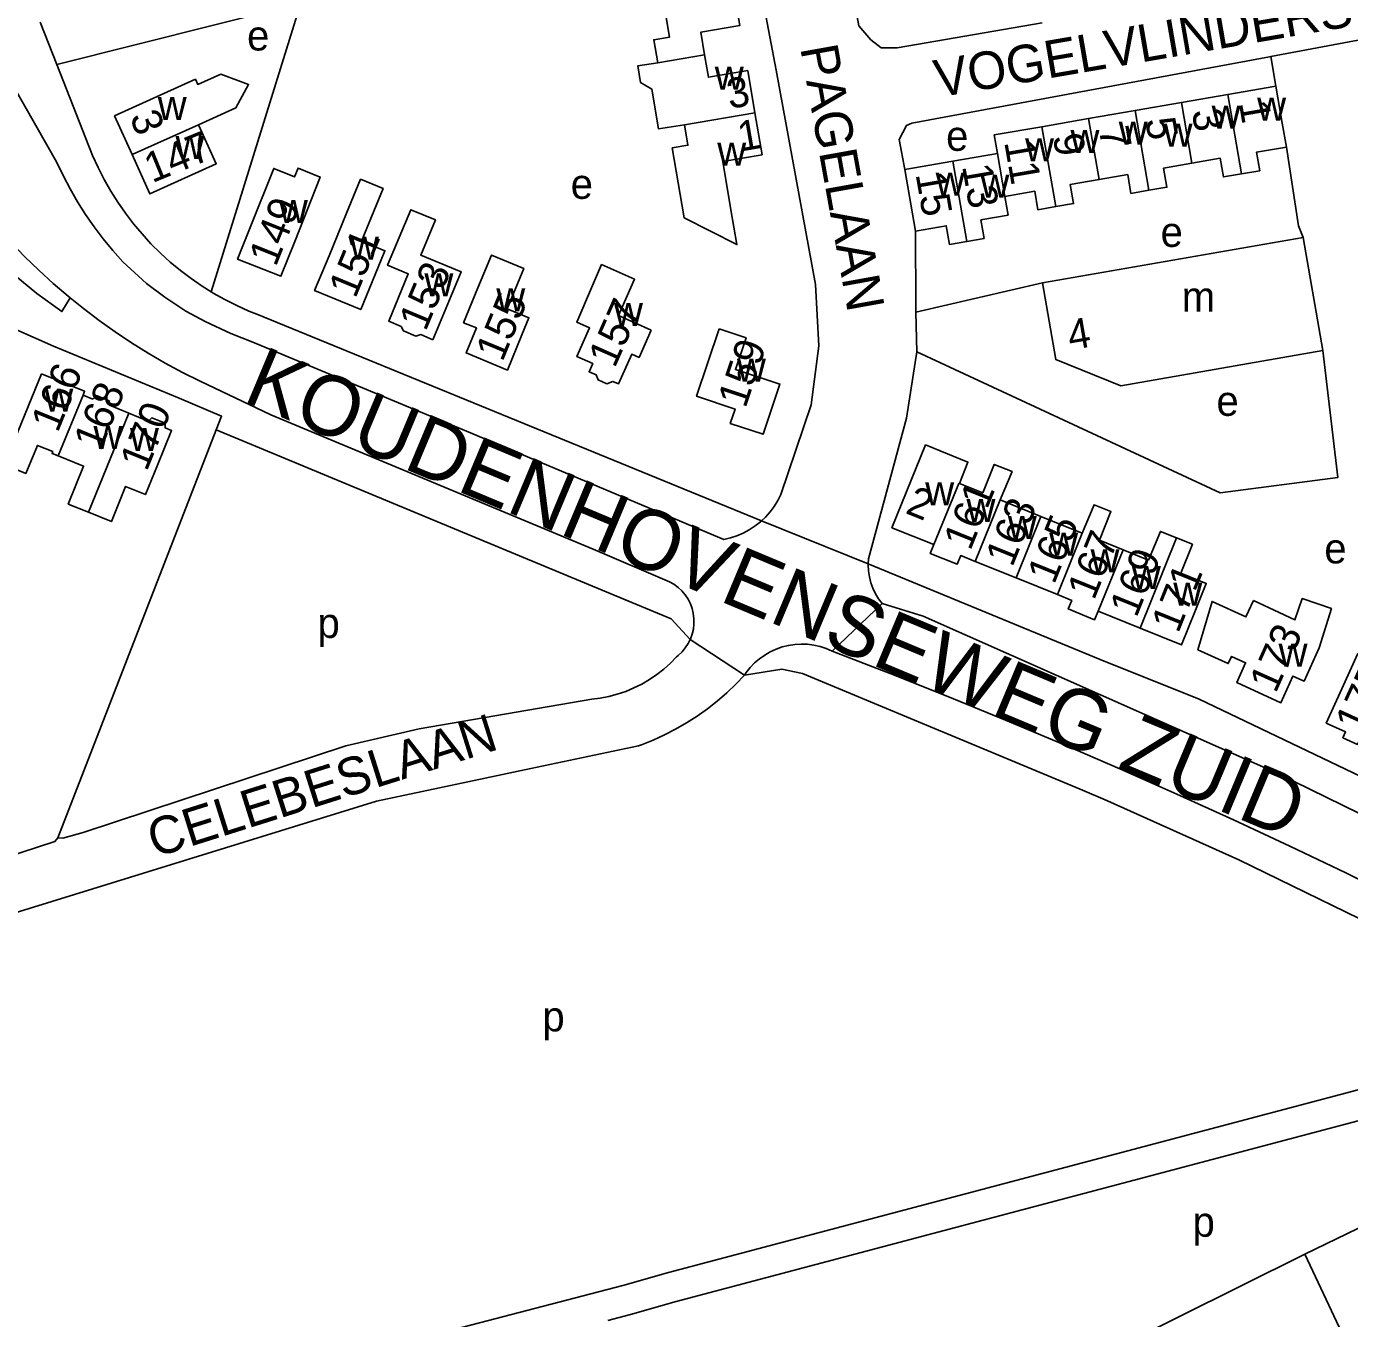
# Model space of a CAD drawing. Extents: x 162883 to 165538, y 383986 to 385172.
# Drawn here: x 163773.3 to 163949.9, y 384457.6 to 384629.9 of the extents above; entities that cross this region are included whole.
import ezdxf

# ---------------------------------------------------------------- set-up
doc = ezdxf.new("R2010")
doc.units = 0
for name, color, linetype in [('BLT_Basislijn', 7, 'Continuous'), ('BLT_Bebouwing', 7, 'Continuous'), ('BLT_Centroide', 7, 'Continuous'), ('BLT_Huisnummer', 7, 'Continuous'), ('BLT_Huisnummer_ tussenligend', 7, 'Continuous'), ('BLT_Onderverdeling_panden', 7, 'Continuous'), ('BLT_Straatnaam', 7, 'Continuous'), ('BLT_Straatnaam_hoofdweg', 7, 'Continuous'), ('BLT_Vlakafsluiter', 7, 'Continuous')]:
    doc.layers.add(name, color=color, linetype=linetype)

msp = doc.modelspace()

# ---------------------------------------------------------------- linework, layer by layer
at = {"layer": 'BLT_Basislijn'}
for p, q in [((163958.25, 384629.46), (163939.36, 384625.95)), ((163940.01, 384621.98), (163939.36, 384625.95)), ((163908.87, 384595.74), (163891.99, 384591.83)), ((163804.01, 384591.55), (163871.37, 384564)), ((163892.11, 384586.56), (163891.99, 384591.83)), ((163771.88, 384589.51), (163776.88, 384587.31)), ((163793.67, 384580.37), (163776.88, 384587.31)), ((163777.47, 384521.73), (163798.62, 384576.13)), ((163885.65, 384558.92), (163885.61, 384558.27)), ((163840.61, 384530.95), (163854.95, 384533.97)), ((163819.98, 384526.61), (163840.61, 384530.95)), ((163743.99, 384503.11), (163819.98, 384526.61)), ((163981.08, 384496.06), (163858.96, 384463.71)), ((163986.23, 384493.28), (163859.99, 384459.84)), ((163952.32, 384470.24), (163943.9, 384466.17)), ((163886.33, 384437.63), (163943.9, 384466.17)), ((163858.96, 384463.71), (163852.89, 384462)), ((163859.99, 384459.84), (163853.91, 384458.13)), ((163850.89, 384457.34), (163853.91, 384458.13))]:
    msp.add_line(p, q, dxfattribs=at)
for points in [[(163719.27, 384682.84), (163723.15, 384676.03), (163756.78, 384615.9), (163761.7, 384607.7), (163765.8, 384602.3), (163770.59, 384597.69), (163774.65, 384594.33)], [(163900.32, 384679.52), (163891.75, 384678.05), (163886.6, 384676.62), (163883.17, 384674.24), (163879.67, 384668.92), (163878.68, 384665.73), (163879, 384658.8), (163884.37, 384630.05), (163885.96, 384628.17), (163887.33, 384627.09), (163889.46, 384627.12), (163908.85, 384630.44)], [(163873.97, 384567.53), (163878.01, 384579.46), (163879.04, 384587.34), (163878.58, 384595.54), (163873.34, 384624.12), (163869.1, 384646.42), (163868.31, 384646.72), (163863.44, 384645.74), (163826.03, 384637.15), (163810.31, 384633.23), (163809.99, 384632.75)], [(163809.99, 384632.75), (163809.03, 384632.82), (163777.35, 384624.88)], [(163797.93, 384594.55), (163809.58, 384632.09), (163809.99, 384632.75)], [(163777.35, 384624.88), (163775.13, 384630.54)], [(163768.58, 384627.54), (163770.13, 384624.47), (163777.3, 384611.88)], [(163782.1, 384612.74), (163777.35, 384624.88)], [(163890.49, 384610.87), (163889.73, 384614.87), (163890.74, 384616.75), (163891.46, 384617.05), (163939.18, 384625.91), (163939.36, 384625.95)], [(163943.67, 384601.8), (163943.02, 384603.35), (163941.42, 384613.87)], [(163782.1, 384612.74), (163782.83, 384611.13), (163783.64, 384609.55), (163784.52, 384608), (163785.46, 384606.5), (163786.48, 384605.05), (163787.56, 384603.64), (163788.7, 384602.28), (163789.9, 384600.97), (163791.15, 384599.72), (163792.47, 384598.52), (163793.83, 384597.39), (163795.25, 384596.32), (163796.71, 384595.32), (163797.93, 384594.55)], [(163777.3, 384611.88), (163778.16, 384610.07), (163779.1, 384608.3), (163780.1, 384606.56), (163781.18, 384604.86), (163782.32, 384603.21), (163783.53, 384601.61), (163784.8, 384600.05), (163786.13, 384598.55), (163789.3, 384595.67), (163791.75, 384593.84), (163794.56, 384591.96), (163797.14, 384590.58), (163800.57, 384588.98), (163803.48, 384587.83)], [(163779.12, 384593.75), (163778.84, 384593.97), (163776.85, 384595.68), (163774.91, 384597.45), (163773.03, 384599.28), (163771.2, 384601.16), (163769.43, 384603.1), (163767.73, 384605.09), (163766.08, 384607.14), (163764.49, 384609.23), (163763.85, 384610.11)], [(163891.91, 384602.65), (163891.96, 384592.7), (163891.99, 384591.83)], [(163774.65, 384594.33), (163778.02, 384591.92), (163779.12, 384593.75)], [(163797.93, 384594.55), (163798.21, 384594.38), (163799.76, 384593.51), (163801.34, 384592.71), (163802.96, 384591.98), (163804.01, 384591.55)], [(163796.45, 384582.62), (163794.11, 384583.8), (163791.8, 384585.05), (163789.53, 384586.37), (163787.3, 384587.76), (163785.12, 384589.21), (163782.98, 384590.73), (163780.89, 384592.32), (163779.12, 384593.75)], [(163803.48, 384587.83), (163832.01, 384575.97), (163866.34, 384561.51)], [(163885.65, 384558.92), (163890.74, 384577.71), (163892.11, 384586.56)], [(163892.11, 384586.56), (163932.58, 384567.72), (163948.31, 384569.79), (163946.3, 384586.72)], [(163796.45, 384582.62), (163805.9, 384578.15), (163848.91, 384560.22), (163859.1, 384555.87)], [(163793.67, 384580.37), (163799.33, 384577.96), (163798.62, 384576.13)], [(163798.62, 384576.13), (163859.3, 384550.93), (163861.85, 384548.16)], [(163873.97, 384567.53), (163873.55, 384566.71), (163873.07, 384565.93), (163872.52, 384565.19), (163871.91, 384564.51), (163871.37, 384564)], [(163871.37, 384564), (163871.24, 384563.88), (163870.52, 384563.31), (163869.75, 384562.8), (163868.95, 384562.37), (163868.1, 384562.01), (163867.23, 384561.72), (163866.34, 384561.51)], [(163885.61, 384558.27), (163916.57, 384545.5), (163929.78, 384540.21), (163963.73, 384523.98), (163999.28, 384506.93)], [(163885.61, 384558.27), (163885.61, 384558.12), (163885.65, 384557.32), (163885.77, 384556.53), (163885.96, 384555.75), (163886.24, 384555), (163886.59, 384554.27), (163887.01, 384553.59), (163887.49, 384552.95)], [(163859.1, 384555.87), (163859.69, 384555.53), (163860.25, 384555.12), (163860.75, 384554.65), (163861.19, 384554.12), (163861.57, 384553.55), (163861.88, 384552.93), (163862.12, 384552.29), (163862.27, 384551.69)], [(163887.49, 384552.95), (163892.95, 384551.29), (163940.28, 384530.29), (163974.99, 384513.31), (163991.55, 384504.84)], [(163862.27, 384551.69), (163862.36, 384550.93), (163862.36, 384550.24), (163862.28, 384549.56), (163862.12, 384548.89), (163861.89, 384548.24), (163861.85, 384548.16)], [(163861.85, 384548.16), (163861.58, 384547.63), (163861.21, 384547.05), (163860.77, 384546.52), (163860.27, 384546.05), (163860.04, 384545.87)], [(163879.2, 384547.23), (163878.36, 384547.42), (163877.51, 384547.53), (163876.66, 384547.56), (163875.81, 384547.51), (163874.96, 384547.38), (163874.13, 384547.17), (163873.32, 384546.89), (163872.55, 384546.53), (163871.81, 384546.1), (163871.11, 384545.61), (163870.46, 384545.05), (163869.87, 384544.43), (163869.34, 384543.76), (163869.1, 384543.41)], [(163880.79, 384546.62), (163880.01, 384546.96), (163879.2, 384547.23)], [(163880.79, 384546.62), (163888.54, 384543.63), (163896.25, 384540.56), (163903.93, 384537.42), (163911.58, 384534.2), (163919.2, 384530.91), (163926.79, 384527.55), (163934.35, 384524.11), (163941.87, 384520.6), (163949.36, 384517.02), (163956.81, 384513.36), (163964.23, 384509.64), (163971.61, 384505.84), (163978.95, 384501.97), (163982.64, 384500)], [(163860.04, 384545.87), (163859.22, 384545.02), (163858.34, 384544.23), (163857.4, 384543.5), (163856.43, 384542.83), (163855.4, 384542.23), (163854.35, 384541.71), (163853.25, 384541.25), (163852.13, 384540.87), (163850.99, 384540.57), (163849.83, 384540.34), (163848.72, 384540.2)], [(163869.1, 384543.41), (163867.94, 384542.2), (163866.73, 384541.05), (163865.46, 384539.95), (163864.15, 384538.91), (163862.78, 384537.94), (163861.37, 384537.04), (163859.92, 384536.2), (163858.43, 384535.44), (163856.91, 384534.74), (163855.36, 384534.12), (163854.95, 384533.97)], [(163869.1, 384543.41), (163874.1, 384544.19), (163876.86, 384543.65), (163913.89, 384528.18), (163917.53, 384526.66), (163935.08, 384518.76), (163954.7, 384509.23), (163966.95, 384503.27), (163978.54, 384497.43), (163981.08, 384496.06)], [(163848.72, 384540.2), (163825.71, 384536.24), (163815.9, 384533.97)], [(163777.47, 384521.73), (163778.15, 384521.66), (163780.85, 384522.42), (163815.9, 384533.97)], [(163777.47, 384521.73), (163777.07, 384521.22), (163752.36, 384513.17)], [(163943.9, 384466.17), (163950.95, 384451.13), (163955.61, 384452.91), (163956.25, 384452.75), (163964.39, 384435.33), (163964.46, 384433.9), (163924.56, 384413.66), (163923.89, 384413.66), (163922.33, 384416.58), (163920.39, 384416.11), (163918.58, 384419.58), (163917.78, 384420.28), (163906.37, 384414.35), (163907.09, 384412.19), (163912.15, 384401.77), (163915.08, 384402.72), (163916.35, 384400.81), (163917.32, 384400.94), (163920.33, 384402.27), (163921.06, 384402.24), (163931.28, 384381.36), (163931.15, 384380.49), (163917.29, 384373.57)], [(163767.22, 384439.42), (163767.75, 384439.83), (163852.89, 384462)]]:
    msp.add_lwpolyline(points, dxfattribs=at)
at = {"layer": 'BLT_Bebouwing'}
for p, q in [((163933.61, 384620.87), (163927.42, 384619.8)), ((163940.01, 384621.98), (163933.61, 384620.87)), ((163927.42, 384619.8), (163921.24, 384618.73)), ((163915.01, 384617.66), (163908.8, 384616.58)), ((163921.24, 384618.73), (163915.01, 384617.66)), ((163896.92, 384611.98), (163890.49, 384610.87)), ((163902.87, 384613.01), (163896.92, 384611.98)), ((163890.49, 384610.87), (163891.91, 384602.65)), ((163943.67, 384601.8), (163946.3, 384586.72)), ((163770.33, 384571.5), (163775.27, 384583.63)), ((163903.21, 384566.78), (163908.67, 384564.58)), ((163908.67, 384564.58), (163914.18, 384562.34)), ((163905.35, 384556.38), (163899.91, 384558.58)), ((163910.87, 384554.15), (163905.35, 384556.38)), ((163921.91, 384549.68), (163916.29, 384551.96))]:
    msp.add_line(p, q, dxfattribs=at)
for points in [[(163863.78, 384626.17), (163863.27, 384629.18), (163868.5, 384630.08), (163867.54, 384635.69)], [(163858.16, 384634.08), (163859.11, 384628.54), (163856.99, 384628.17), (163857.52, 384625.1)], [(163870.5, 384618.45), (163869.54, 384624.06), (163864.3, 384623.17), (163863.78, 384626.17)], [(163857.52, 384625.1), (163854.85, 384624.68), (163855.23, 384622.47), (163856.73, 384621.6), (163857.64, 384616.28), (163861.1, 384616.84)], [(163787.38, 384612.86), (163785.04, 384618.02), (163795.82, 384622.91), (163796.14, 384622.21), (163799.24, 384623.59), (163802.93, 384622.21), (163801.24, 384619.11), (163796.26, 384616.82)], [(163941.42, 384613.87), (163940.87, 384617.05), (163940.01, 384621.98)], [(163861.1, 384616.84), (163861.56, 384614.11), (163859.47, 384613.75), (163861.07, 384604.41), (163868.1, 384600.85), (163867.3, 384605.48), (163866.2, 384611.93), (163871.46, 384612.83), (163870.5, 384618.45)], [(163796.26, 384616.82), (163798.62, 384611.64), (163789.76, 384607.61), (163787.38, 384612.86)], [(163908.8, 384616.58), (163902.44, 384615.48), (163902.87, 384613.01)], [(163935.44, 384610.28), (163937.86, 384610.7), (163937.43, 384613.18), (163941.42, 384613.87)], [(163928.81, 384611.72), (163932.6, 384612.37), (163933.03, 384609.87), (163935.44, 384610.28)], [(163809.08, 384601.26), (163812.48, 384609.85), (163809.52, 384611.06), (163809.07, 384609.88), (163806.29, 384611.02), (163803.32, 384603.56), (163801.46, 384598.92), (163807.23, 384596.62), (163809.08, 384601.26)], [(163916.42, 384609.54), (163920.25, 384610.2), (163920.68, 384607.68), (163923.08, 384608.09)], [(163923.08, 384608.09), (163925.47, 384608.51), (163925.03, 384611.06), (163928.81, 384611.72)], [(163819.81, 384596.85), (163817.89, 384592.19), (163811.74, 384594.72), (163813.66, 384599.36), (163816.01, 384605.06), (163817.87, 384609.57), (163820.87, 384608.34), (163819.01, 384603.82), (163817.98, 384601.32), (163821.12, 384600.02), (163819.81, 384596.85)], [(163910.65, 384605.92), (163913.02, 384606.33), (163912.58, 384608.87), (163916.42, 384609.54)], [(163898.77, 384601.28), (163901.08, 384601.68), (163900.65, 384604.15), (163904.28, 384604.78), (163903.85, 384607.28)], [(163903.85, 384607.28), (163907.85, 384607.97), (163908.27, 384605.51), (163910.65, 384605.92)], [(163827.52, 384588.16), (163825.91, 384588.84), (163825.26, 384588.64), (163823.59, 384589.34), (163823.27, 384589.93), (163821.64, 384590.62), (163824.24, 384596.94), (163821.48, 384598.1), (163824.58, 384605.49), (163827.86, 384604.15), (163825.91, 384599.46), (163831.31, 384597.2), (163827.52, 384588.16)], [(163891.91, 384602.65), (163896.03, 384603.36), (163896.46, 384600.88), (163898.77, 384601.28)], [(163908.87, 384595.74), (163943.67, 384601.8)], [(163839.41, 384588.82), (163840.34, 384591.08), (163837.42, 384592.29), (163839.64, 384597.68), (163835.34, 384599.45), (163833.54, 384595.08), (163831.62, 384590.43), (163833.32, 384589.73), (163831.94, 384586.4), (163837.47, 384584.12), (163839.41, 384588.82)], [(163856.64, 384589.45), (163852.28, 384591.38), (163854.43, 384596.23), (163850.04, 384598.18), (163848.71, 384595.09), (163846.73, 384590.49), (163848.43, 384589.74), (163846.74, 384585.91), (163848.85, 384584.97), (163848.37, 384583.89), (163849.32, 384583.47), (163849.57, 384582.81), (163850.73, 384582.29), (163851.53, 384582.6), (163852.29, 384582.27), (163854.05, 384586.24), (163855.03, 384585.81), (163856.64, 384589.45)], [(163946.3, 384586.72), (163919.33, 384581.99), (163910.65, 384585.5), (163908.87, 384595.74)], [(163865.73, 384589.61), (163862.72, 384580.61), (163867.84, 384578.9), (163867.21, 384577), (163871.59, 384575.54), (163873.83, 384582.24), (163867.9, 384584.18), (163869.31, 384588.41), (163865.73, 384589.61)], [(163775.27, 384583.63), (163781.03, 384581.28), (163780.83, 384580.78)], [(163780.83, 384580.78), (163782.14, 384580.25), (163782.62, 384580.71), (163784.3, 384580.02), (163784.37, 384579.41), (163786.95, 384578.36)], [(163781.56, 384565.15), (163784.62, 384563.91), (163786.51, 384568.58), (163789.15, 384567.51), (163790.75, 384571.42), (163792.64, 384576.05), (163791.8, 384576.39), (163791.77, 384577.04), (163790, 384577.76), (163789.54, 384577.3), (163786.95, 384578.36)], [(163777.52, 384572.67), (163776.7, 384573), (163776.8, 384573.24), (163774.74, 384574.07), (163773.21, 384570.32), (163770.33, 384571.5)], [(163894.37, 384560.82), (163888.79, 384563.08), (163893.27, 384574.13), (163898.93, 384571.83), (163897.78, 384568.98)], [(163777.52, 384572.67), (163780.91, 384571.3), (163778.86, 384566.24), (163781.56, 384565.15)], [(163897.78, 384568.98), (163900.9, 384567.72), (163902.44, 384571.53), (163904.81, 384570.58), (163903.21, 384566.78)], [(163914.18, 384562.34), (163915.76, 384566.14), (163918.01, 384565.24), (163916.47, 384561.42), (163919.66, 384560.13)], [(163919.66, 384560.13), (163923.01, 384558.77), (163924.61, 384562.58), (163926.74, 384561.73)], [(163899.91, 384558.58), (163897.96, 384559.37), (163897.5, 384558.23), (163893.9, 384559.66), (163894.37, 384560.82)], [(163926.74, 384561.73), (163928.88, 384560.87), (163927.32, 384557.03), (163930.74, 384555.65), (163929.3, 384552.09), (163927.43, 384547.45), (163921.91, 384549.68)], [(163916.29, 384551.96), (163915.82, 384550.8), (163912.32, 384552.24), (163912.78, 384553.37), (163910.87, 384554.15)], [(163959.67, 384544.41), (163955.12, 384546.48), (163954.34, 384544.76), (163950.97, 384546.3), (163948.82, 384541.57), (163946.74, 384537.02), (163949.32, 384535.85), (163948.96, 384535.06), (163950.92, 384534.17), (163951.29, 384534.98), (163951.9, 384534.7), (163953.98, 384539.25)]]:
    msp.add_lwpolyline(points, dxfattribs=at)
msp.add_lwpolyline([(163937.03, 384553.36), (163942.57, 384550.78), (163943.55, 384553.63), (163947.43, 384552.3), (163945.79, 384547.04), (163943.81, 384542.61), (163942.28, 384543.29), (163940.69, 384539.73), (163934.79, 384542.44), (163935.97, 384545.07), (163934.11, 384545.92), (163933.66, 384544.95), (163929.62, 384546.8), (163931.51, 384553.25), (163936.03, 384551.18)], close=True, dxfattribs=at)
at = {"layer": 'BLT_Onderverdeling_panden'}
for p, q in [((163863.78, 384626.17), (163857.52, 384625.1)), ((163935.44, 384610.28), (163933.61, 384620.87)), ((163928.81, 384611.72), (163927.42, 384619.8)), ((163870.5, 384618.45), (163861.1, 384616.84)), ((163916.42, 384609.54), (163915.01, 384617.66)), ((163923.08, 384608.09), (163921.24, 384618.73)), ((163796.26, 384616.82), (163787.38, 384612.86)), ((163910.65, 384605.92), (163908.8, 384616.58)), ((163898.77, 384601.28), (163896.92, 384611.98)), ((163902.87, 384613.01), (163903.85, 384607.28)), ((163780.83, 384580.78), (163777.52, 384572.67)), ((163786.95, 384578.36), (163781.56, 384565.15)), ((163899.91, 384558.58), (163903.21, 384566.78)), ((163905.35, 384556.38), (163908.67, 384564.58)), ((163910.87, 384554.15), (163914.18, 384562.34)), ((163921.91, 384549.68), (163926.74, 384561.73)), ((163916.29, 384551.96), (163919.66, 384560.13))]:
    msp.add_line(p, q, dxfattribs=at)
msp.add_lwpolyline([(163894.37, 384560.82), (163897.73, 384569), (163897.78, 384568.98)], dxfattribs=at)
at = {"layer": 'BLT_Vlakafsluiter'}
for p, q in [((163885.61, 384558.27), (163871.37, 384564)), ((163880.79, 384546.62), (163887.49, 384552.95)), ((163861.85, 384548.16), (163869.1, 384543.41))]:
    msp.add_line(p, q, dxfattribs=at)

# ---------------------------------------------------------------- texts
at = {"layer": 'BLT_Centroide'}
for s, p in [('e', (163802.72, 384626.74)), ('w', (163865.14, 384621.5)), ('w', (163790.8, 384617.47)), ('w', (163931.44, 384616.33)), ('w', (163937.52, 384617.38)), ('w', (163919.05, 384614.17)), ('e', (163896.01, 384613.36)), ('w', (163912.61, 384613.06)), ('w', (163925.03, 384613.91)), ('w', (163793.16, 384612.28)), ('w', (163865.47, 384611.38)), ('w', (163906.55, 384611.97)), ('w', (163894.62, 384607.36)), ('w', (163900.59, 384607.11)), ('e', (163845.91, 384606.95)), ('w', (163806.97, 384603.73)), ('e', (163924.64, 384600.54)), ('w', (163816.44, 384598.83)), ('w', (163826.39, 384593.94)), ('w', (163835.98, 384591.95)), ('m', (163927.46, 384591.91)), ('w', (163851.69, 384589.98)), ('w', (163868.09, 384582.56)), ('w', (163775.67, 384578.58)), ('e', (163932.09, 384578)), ('w', (163782.23, 384573.56)), ('w', (163787.09, 384573.31)), ('w', (163893.22, 384566.06)), ('w', (163898.73, 384563.83)), ('w', (163904.25, 384561.59)), ('w', (163909.77, 384559.36)), ('e', (163946.49, 384558.32)), ('w', (163915.28, 384557.14)), ('w', (163920.8, 384554.89)), ('w', (163926.33, 384552.67)), ('p', (163812.12, 384548.38)), ('w', (163940.38, 384544.53)), ('p', (163842.13, 384495.89)), ('p', (163928.9, 384468.49))]:
    msp.add_text(s, height=4, dxfattribs=at).set_placement(p)
at = {"layer": 'BLT_Huisnummer'}
for s, rotation, p in [('1', 279.8045, (163935.07, 384619.77)), ('3', 290.2731, (163787.03, 384617.93)), ('1', 9.711, (163868.55, 384613.26)), ('5', 279.8045, (163922.58, 384617.51)), ('147', 22.2731, (163790.06, 384609.03)), ('9', 279.8045, (163910.24, 384615.35)), ('15', 279.8045, (163891.93, 384610.25)), ('149', 68.2731, (163806.55, 384597.78)), ('151', 67.5766, (163817.17, 384593.55)), ('153', 67.2866, (163826.55, 384589.17)), ('155', 67.5776, (163836.8, 384585.1)), ('157', 66.1111, (163851.78, 384584.26)), ('4', 9.9445, (163912.59, 384586.75)), ('159', 71.5436, (163869.24, 384578.91)), ('166', 67.8002, (163777.45, 384575.65)), ('170', 67.8006, (163789.32, 384570.48)), ('2', 337.9724, (163890.43, 384565.08)), ('163', 67.9711, (163904.84, 384557.71)), ('167', 67.9711, (163915.75, 384553.29)), ('171', 67.9711, (163926.98, 384548.88)), ('173', 65.8794, (163939.99, 384540.88)), ('175', 65.4698, (163951.42, 384535.51))]:
    msp.add_text(s, height=4, rotation=rotation, dxfattribs=at).set_placement(p)
at = {"layer": 'BLT_Huisnummer_ tussenligend'}
for s, rotation, p in [('3', 9.711, (163867.11, 384618.95)), ('3', 279.8045, (163928.78, 384618.66)), ('7', 279.8045, (163916.37, 384616.31)), ('11', 279.8045, (163903.76, 384614.53)), ('13', 279.8045, (163898.14, 384611.32)), ('168', 67.8002, (163783.14, 384573.14)), ('161', 67.9711, (163899.24, 384559.9)), ('165', 67.9711, (163910.43, 384555.41)), ('169', 67.9711, (163921.41, 384550.97))]:
    msp.add_text(s, height=4, rotation=rotation, dxfattribs=at).set_placement(p)
at = {"layer": 'BLT_Straatnaam'}
for s, height, rotation, p in [('VOGELVLINDERSTRAAT', 4.9999, 9.7924, (163894.91, 384620.46)), ('PAGELAAN', 5, 280.2113, (163876.53, 384627.11)), ('CELEBESLAAN', 5, 17.5257, (163790.41, 384519.03))]:
    msp.add_text(s, height=height, rotation=rotation, dxfattribs=at).set_placement(p)
at = {"layer": 'BLT_Straatnaam_hoofdweg'}
msp.add_text('KOUDENHOVENSEWEG ZUID', height=8, rotation=337.2536, dxfattribs=at).set_placement((163801.97, 384580.05))

doc.saveas('drawing.dxf')
